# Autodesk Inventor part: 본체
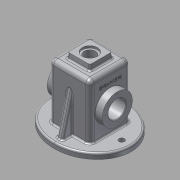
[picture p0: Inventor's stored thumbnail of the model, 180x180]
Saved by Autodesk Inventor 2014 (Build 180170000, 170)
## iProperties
Created: 2017-07
Part Number: 본체
Material: 알루미늄 6061
Document SubType Name: Modeling
Designer: 702-10
Density: 2.71 g/cm^3
Appearance: 알루미늄 - 평지
Mass: 896.814 g
Surface Area: 989.073 cm^2
Volume: 330.928 cm^3
Author: 702-10
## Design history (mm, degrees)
sketch "스케치1"
  geometry: L1 (-37, 37)-(37, 37); L2 (37, 37)-(37, -37); L3 (37, -37)-(-37, -37); L4 (-37, -37)-(-37, 37); L5 (-37, 37)-(37, -37); L6 (37, 37)-(-37, -37); 1 further point
  constraints: 12 end point, 2 midpoint, 2 parallel, 1 horizontal, 1 perpendicular
  dimensions: "d1" = 74 distance of L1.end L2.end; "d2" = 74 distance of L2.end L3.end
extrude "돌출1" new body sketch "스케치1" distance "d3" = 110; taper "d4" = 0 deg
sketch "스케치2"
  geometry: L1 (37, -37)-(37, 37) reference; L2 (0, 0)-(0, 65); L3 (0, 0)-(75, 0); 1 further point; 1 other entity
  constraints: 4 end point, 1 coincident, 1 horizontal, 1 parallel, 1 perpendicular, 4 other
  dimensions: "d7" = 65 distance of L2.start L2.end; "d8" = 75 distance of L2.start L3.end
extrude "돌출2" join sketch "스케치2" distance "d9" = 10; taper "d10" = 0 deg
fillet "모깎기1" dims "d11" = 8
fillet "모깎기2" dims "d12" = 8
feature "쉘1" dims "d13" = 10, "d14" = 5
sketch "스케치3"
  geometry: L1 (-29, 110)-(29, 110) reference; L2 (37, 102)-(37, 10) reference; L3 (37, 10)-(75, 10) reference; L4 (75, 10)-(75, 0) reference; L5 (75, 0)-(32, 0) reference; L6 (32, 0)-(32, 102) reference; L7 (29, 105)-(-29, 105) reference; L8 (-32, 102)-(-32, 0) reference; L9 (-32, 0)-(-75, 0) reference; L10 (-75, 0)-(-75, 10) reference; L11 (-75, 10)-(-37, 10) reference; L12 (-37, 10)-(-37, 102) reference; L13 (0, 0)-(0, 55); L14 (0, 55)-(-32, 55); L15 (0, 55)-(32, 55); L16 (32, 82.5)-(24.202, 76.156); L17 (24.202, 76.156)-(24.202, 55); L18 (-32, 82.5)-(-25, 75.5); L19 (-25, 75.5)-(-25, 55); L20 (-32, 82.5)-(-32, 55); A1 r 8 centre (-29, 102) between (-29, 110) and (-37, 102) reference; A2 r 8 centre (29, 102) between (37, 102) and (29, 110) reference; A3 r 3 centre (29, 102) between (32, 102) and (29, 105) reference; A4 r 3 centre (-29, 102) between (-29, 105) and (-32, 102) reference
  constraints: 16 end point, 6 point on line, 4 perpendicular, 1 parallel
  dimensions: "d15" = 55 distance of L13.start L13.end; "d16" = 55 diameter of L16.start L15; "d17" = 7 distance between parallel lines of L19 L8; "d18" = 55 diameter of L18.start L14; "d19" = 135 deg angle of L19 L18
revolve "회전1" sketch "스케치3" stored, may be unused: angle "d20" = 90 deg
fillet "모깎기3" dims "d21" = 0.5
sketch "스케치4"
  geometry: L1 (-37, 29)-(-37, -29) reference; L2 (-58, 0)-(58, 0); C1 r 5 at (-58, 0); C2 r 5 at (58, 0); 2 further points; 1 other entity
  constraints: 3 coincident, 2 centre point, 2 end point, 1 midpoint, 1 perpendicular, 1 other
  dimensions: "d22" = 116 distance of L2.start L2.end; "d23" = 10 diameter of C1; "d24" = 10 diameter of C2
extrude "돌출3" cut sketch "스케치4" stored distance "d25" = 10; taper "d26" = 0 deg
fillet "모깎기4" dims "d27" = 3
sketch "스케치5"
  geometry: L1 (58, 92)-(58, 0) reference; L2 (29, -10)-(29, 45); C1 r 27.5 at (29, 45)
  constraints: 2 end point, 1 centre point, 1 coincident, 1 parallel
  dimensions: "d28" = 55 distance of L2.start L2.end; "d29" = 55 diameter of C1
extrude "돌출4" join sketch "스케치5" distance "d30" = 13; taper "d31" = 0 deg
fillet "모깎기5" dims "d32" = 0.5
sketch "스케치6"
  geometry: C1 r 27.5 at (0, 0) reference; C2 r 16 at (0, 0); 1 further point
  constraints: 1 centre point, 1 coincident
  dimensions: "d33" = 32 diameter of C2
extrude "돌출5" cut sketch "스케치6" stored distance "d34" = 13; taper "d35" = 0 deg
node "작업 평면1"
sketch "스케치7"
  geometry: L1 (20, -20)-(-20, -20); L2 (-20, -20)-(-20, 20); L3 (-20, 20)-(20, 20); L4 (20, 20)-(20, -20); L5 (20, -20)-(-20, 20); L6 (-20, -20)-(20, 20); 1 further point
  constraints: 12 end point, 2 midpoint, 2 parallel, 1 horizontal, 1 perpendicular
  dimensions: "d37" = 40 distance of L2.end L3.end; "d38" = 40 distance of L1.end L2.end
extrude "돌출6" join sketch "스케치7" stored distance "d39" = 13; taper "d40" = 5 deg
fillet "모깎기6" dims "d41" = 3
fillet "모깎기7" dims "d42" = 3
sketch "스케치8"
  geometry: 2 further points
  constraints: 1 coincident
hole "구멍1" sketch "스케치8" at (0, 0) diameter "d43" = 21; stored, may be unused: countersink angle "d47" = 90 deg, drill point angle "d49" = 118 deg; dims "d44" = 6, "d45" = 28, "d46" = 4, "d48" = 8
fillet "모깎기8" dims "d50" = 3
sketch "스케치9" dims "d51" = 45
  geometry: C1 r 27.5 at (0, 0) reference; 3 further points
  constraints: 2 vertical alignment, 1 coincident, 2 other
hole "구멍2" sketch "스케치9" at (0, 22.5) diameter "d52" = 3.242; stored, may be unused: countersink angle "d56" = 90 deg, drill point angle "d58" = 118 deg; dims "d53" = 8, "d54" = 28, "d55" = 4, "d57" = 10
sketch "스케치10"
  geometry: L1 (0, -32)-(102, -32) reference; L2 (105, -29)-(105, -10.5) reference; L3 (105, -10.5)-(116, -10.5) reference; L4 (116, -10.5)-(116, -14) reference; L5 (116, -14)-(120, -14) reference; L6 (120, -14)-(120, -20) reference; L7 (120, -20)-(112.739, -20.635) reference; L8 (110, -23.624)-(110, -29) reference; L9 (102, -37)-(13, -37) reference; L10 (10, -40)-(10, -62) reference; L11 (7, -65)-(0, -65) reference; L12 (0, -65)-(0, -32) reference; L13 (102, 32)-(0, 32) reference; L14 (0, 32)-(0, 65) reference; L15 (0, 65)-(7, 65) reference; L16 (10, 62)-(10, 40) reference; L17 (13, 37)-(102, 37) reference; L18 (110, 29)-(110, 23.624) reference; L19 (112.739, 20.635)-(120, 20) reference; L20 (120, 20)-(120, 14) reference; L21 (120, 14)-(116, 14) reference; L22 (116, 14)-(116, 10.5) reference; L23 (116, 10.5)-(105, 10.5) reference; L24 (105, 10.5)-(105, 29) reference; L25 (10, 55)-(82.194, 37); A1 r 3 centre (102, -29) between (102, -32) and (105, -29) reference; A2 r 3 centre (113, -23.624) between (112.739, -20.635) and (110, -23.624) reference; A3 r 8 centre (102, -29) between (102, -37) and (110, -29) reference; A4 r 3 centre (13, -40) between (13, -37) and (10, -40) reference; A5 r 3 centre (13, 40) between (10, 40) and (13, 37) reference; A6 r 8 centre (102, 29) between (110, 29) and (102, 37) reference; A7 r 3 centre (113, 23.624) between (110, 23.624) and (112.739, 20.635) reference; A8 r 3 centre (102, 29) between (105, 29) and (102, 32) reference; 1 further point
  constraints: 2 end point, 2 point on line, 2 other
  dimensions: "d62" = 10 distance from line of L25.start L15; "d63" = 14 deg angle of L15 L25
feature "리브1" sketch "스케치10" dims "d64" = 1, "d65" = 10, "d66" = 0, "d67" = 0, "d68" = 1, "d69" = 1
fillet "모깎기9" dims "d70" = 3
fillet "모깎기10" dims "d71" = 3
fillet "모깎기11" dims "d72" = 3
fillet "모깎기12" dims "d73" = 3
node "작업 평면2"
sketch "스케치11"
  geometry: L1 (46.011, 18)-(11.989, 18) reference; L2 (66, -89)-(66, 0) reference; 2 further points
  constraints: 1 other
  dimensions: "d75" = 30 distance from line of L1 point (29, -12); "d76" = 37 distance from line of point (29, -12) L2
feature "엠보싱1" sketch "스케치11" dims "d77" = 0.5, "d78" = 0
chamfer "모따기1" distance "d79" = 1; stored, may be unused: second distance "d80" = 2, angle "d81" = 45 deg
node "솔리드1"
mirror "대칭1"
mirror "대칭2"
pattern_circular "원형 패턴1" dims angle "d60" = 360 deg
mirror "대칭3"
mirror "대칭4"
node "절단 모서리 투영1"
node "절단 모서리 투영2"
other parameters: "d74" = 18.75
